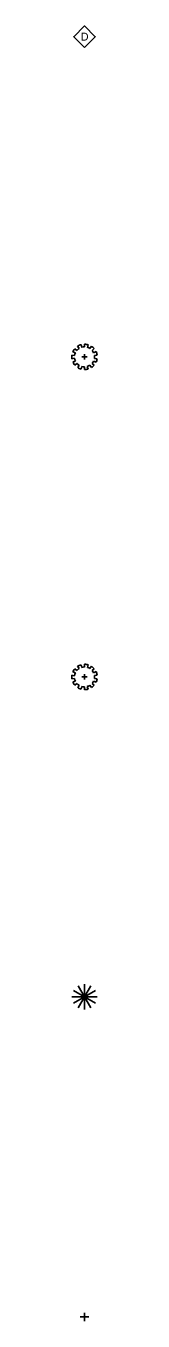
# Model space of a CAD drawing. Extents: x 98 to 2902, y -6 to 903.
# Drawn here: x 2498 to 2502, y -0.6 to 201.7 of the extents above; entities that cross this region are included whole.
import ezdxf

# ---------------------------------------------------------------- set-up
doc = ezdxf.new("R2010")
doc.units = 0
for name, color, linetype in [('V-SITE-OTLN', 7, 'Continuous'), ('V-SITE-VEGE', 7, 'Continuous'), ('V-STRM-DEVC', 7, 'Continuous')]:
    doc.layers.add(name, color=color, linetype=linetype)

msp = doc.modelspace()

# ---------------------------------------------------------------- linework, layer by layer
at = {"layer": 'V-SITE-OTLN'}
for p, q in [((2500, 0.65), (2500, -0.65)), ((2500, 0), (2499.35, 0)), ((2500, 0), (2500.65, 0))]:
    msp.add_line(p, q, dxfattribs=at)
at = {"layer": 'V-SITE-VEGE'}
for p, q in [((2499.46, 151.89), (2499.56, 151.47)), ((2500, 151.53), (2500.01, 151.96)), ((2500.57, 151.88), (2500.45, 151.47)), ((2498.03, 150.25), (2498.46, 150.18)), ((2498.46, 149.76), (2498.04, 149.69)), ((2498.58, 150.61), (2498.19, 150.78)), ((2498.49, 151.26), (2498.81, 150.98)), ((2499.17, 151.3), (2498.93, 151.65)), ((2499.58, 150), (2500.42, 150)), ((2500, 150.42), (2500, 149.58)), ((2500.84, 151.29), (2501.08, 151.64)), ((2501.51, 151.27), (2501.19, 150.99)), ((2501.42, 150.62), (2501.8, 150.82)), ((2501.97, 150.25), (2501.54, 150.19)), ((2501.54, 149.75), (2501.97, 149.7)), ((2498.19, 149.16), (2498.58, 149.35)), ((2498.83, 148.96), (2498.5, 148.68)), ((2498.94, 148.3), (2499.15, 148.68)), ((2499.58, 148.48), (2499.46, 148.07)), ((2500, 147.99), (2500, 148.42)), ((2500.43, 148.49), (2500.56, 148.08)), ((2501.08, 148.31), (2500.85, 148.68)), ((2501.17, 148.95), (2501.5, 148.68)), ((2501.81, 149.15), (2501.41, 149.31)), ((2498.49, 101.26), (2498.81, 100.98)), ((2499.17, 101.3), (2498.93, 101.65)), ((2499.46, 101.89), (2499.56, 101.47)), ((2500, 101.53), (2500.01, 101.96)), ((2500.57, 101.88), (2500.45, 101.47)), ((2500.84, 101.29), (2501.08, 101.64)), ((2501.51, 101.27), (2501.19, 100.99)), ((2498.03, 100.25), (2498.46, 100.18)), ((2498.46, 99.76), (2498.04, 99.69)), ((2498.58, 100.61), (2498.19, 100.78)), ((2498.19, 99.16), (2498.58, 99.35)), ((2499.58, 100), (2500.42, 100)), ((2500, 100.42), (2500, 99.58)), ((2501.81, 99.15), (2501.41, 99.31)), ((2501.42, 100.62), (2501.8, 100.82)), ((2501.97, 100.25), (2501.54, 100.19)), ((2501.54, 99.75), (2501.97, 99.7)), ((2498.83, 98.96), (2498.5, 98.68)), ((2498.94, 98.3), (2499.15, 98.68)), ((2499.58, 98.48), (2499.46, 98.07)), ((2500, 97.99), (2500, 98.42)), ((2500.43, 98.49), (2500.56, 98.08)), ((2501.08, 98.31), (2500.85, 98.68)), ((2501.17, 98.95), (2501.5, 98.68)), ((2500, 50), (2498.28, 50.99)), ((2500, 50), (2499.01, 51.72)), ((2500, 51.98), (2500, 50)), ((2500, 50), (2500.99, 51.72)), ((2500, 50), (2501.72, 50.99)), ((2498.02, 50), (2500, 50)), ((2500, 50), (2498.28, 49.01)), ((2500, 50), (2499.01, 48.28)), ((2500, 50), (2500.99, 48.28)), ((2500, 50), (2501.72, 49.01)), ((2500, 50), (2500, 48.02)), ((2500, 50), (2501.98, 50))]:
    msp.add_line(p, q, dxfattribs=at)
for centre, radius, start, end in [((2500, 149.98), 1.98, 105.972, 122.5562), ((2500, 149.98), 1.98, 73.2952, 89.5718), ((2500, 149.98), 1.98, 172.27, 188.583), ((2500, 149.98), 1.98, 139.7777, 156.0738), ((2500, 149.98), 1.56, 156.0557, 172.7558), ((2500, 149.98), 1.56, 188.0619, 204.0332), ((2500, 149.98), 1.56, 122.254, 140.086), ((2500, 149.98), 1.56, 89.9461, 106.3473), ((2500, 149.98), 1.56, 57.451, 73.0843), ((2500, 149.98), 1.98, 40.7122, 57.1166), ((2500, 149.98), 1.56, 24.4529, 40.4774), ((2500, 149.98), 1.56, 351.5431, 7.6203), ((2500, 149.98), 1.98, 7.9671, 24.8625), ((2500, 149.98), 1.98, 204.5394, 220.9852), ((2500, 149.98), 1.56, 221.2062, 236.7795), ((2500, 149.98), 1.98, 237.6108, 254.1981), ((2500, 149.98), 1.56, 254.31, 270.043), ((2500, 149.98), 1.98, 270.0356, 286.342), ((2500, 149.98), 1.56, 285.9559, 303.0564), ((2500, 149.98), 1.98, 302.8434, 319.0222), ((2500, 149.98), 1.56, 318.6432, 334.5795), ((2500, 149.98), 1.98, 335.3123, 351.7042), ((2500, 99.98), 1.98, 139.7777, 156.0738), ((2500, 99.98), 1.56, 122.254, 140.086), ((2500, 99.98), 1.98, 105.972, 122.5562), ((2500, 99.98), 1.56, 89.9461, 106.3473), ((2500, 99.98), 1.98, 73.2952, 89.5718), ((2500, 99.98), 1.56, 57.451, 73.0843), ((2500, 99.98), 1.98, 40.7122, 57.1166), ((2500, 99.98), 1.98, 172.27, 188.583), ((2500, 99.98), 1.98, 204.5394, 220.9852), ((2500, 99.98), 1.56, 156.0557, 172.7558), ((2500, 99.98), 1.56, 188.0619, 204.0332), ((2500, 99.98), 1.56, 318.6432, 334.5795), ((2500, 99.98), 1.56, 24.4529, 40.4774), ((2500, 99.98), 1.56, 351.5431, 7.6203), ((2500, 99.98), 1.98, 7.9671, 24.8625), ((2500, 99.98), 1.98, 335.3123, 351.7042), ((2500, 99.98), 1.56, 221.2062, 236.7795), ((2500, 99.98), 1.98, 237.6108, 254.1981), ((2500, 99.98), 1.56, 254.31, 270.043), ((2500, 99.98), 1.98, 270.0356, 286.342), ((2500, 99.98), 1.56, 285.9559, 303.0564), ((2500, 99.98), 1.98, 302.8434, 319.0222)]:
    msp.add_arc(centre, radius, start, end, dxfattribs=at)
at = {"layer": 'V-STRM-DEVC'}
msp.add_lwpolyline([(2500, 198.32), (2501.68, 200), (2500, 201.68), (2498.32, 200)], close=True, dxfattribs=at)

# ---------------------------------------------------------------- texts
msp.add_text('D', height=1.25, dxfattribs=at).set_placement((2499.42, 199.38))

doc.saveas('drawing.dxf')
